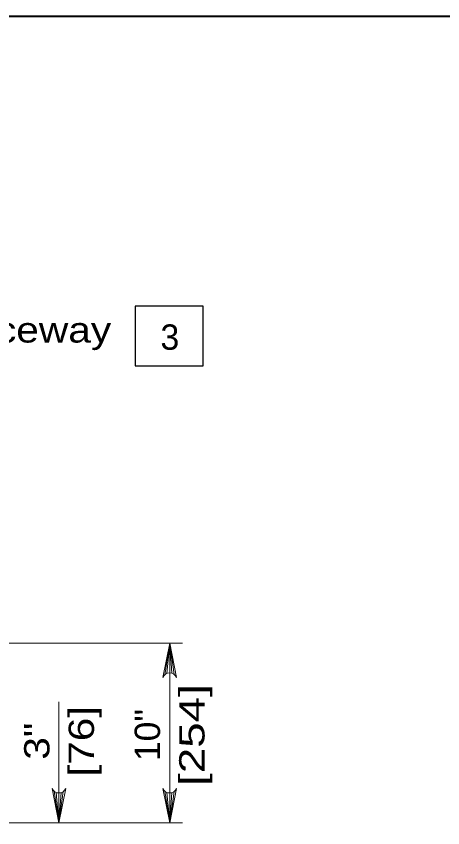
# Model space of a CAD drawing. Extents: x 1083.1 to 1123, y 697.4 to 741.4.
# Drawn here: x 1092.929 to 1095.554, y 713.855 to 718.854 of the extents above; entities that cross this region are included whole.
import ezdxf
from ezdxf.enums import TextEntityAlignment as Align

# ---------------------------------------------------------------- set-up
doc = ezdxf.new("R2010")
doc.units = 0
doc.header["$LTSCALE"] = 0.062
doc.layers.add('1', color=7, linetype='Continuous', lineweight=13)

msp = doc.modelspace()

# ---------------------------------------------------------------- linework, layer by layer
at = {"layer": '1', "lineweight": 25}
msp.add_line((1085.12642, 718.85408), (1116.62642, 718.85408), dxfattribs=at)
at = {"layer": '1'}
for p, q in [((1091.74475, 714.99225), (1093.95242, 714.99225)), ((1093.84408, 714.79808), (1093.87375, 714.99225)), ((1093.8565, 714.80542), (1093.87375, 714.99225)), ((1093.87375, 713.88608), (1093.87375, 714.99225)), ((1093.87375, 714.80883), (1093.87375, 714.99225)), ((1093.88733, 714.80683), (1093.87375, 714.99225)), ((1093.90058, 714.80033), (1093.87375, 714.99225)), ((1093.1915, 713.88608), (1093.1915, 714.63117)), ((1093.16175, 714.08033), (1093.1915, 713.88608)), ((1093.17425, 714.073), (1093.1915, 713.88608)), ((1093.21833, 714.07808), (1093.1915, 713.88608)), ((1093.205, 714.07158), (1093.1915, 713.88608)), ((1093.84408, 714.08033), (1093.87375, 713.88608)), ((1093.8565, 714.073), (1093.87375, 713.88608)), ((1093.90058, 714.07808), (1093.87375, 713.88608)), ((1093.88733, 714.07158), (1093.87375, 713.88608)), ((1093.1915, 714.06958), (1093.1915, 713.88608)), ((1093.87375, 714.06958), (1093.87375, 713.88608)), ((1092.35375, 713.88608), (1093.95242, 713.88608))]:
    msp.add_line(p, q, dxfattribs=at)
at = {"layer": '1', "lineweight": 40}
msp.add_lwpolyline([(1085.12642, 718.85408), (1116.62642, 718.85408), (1116.62642, 697.85408), (1085.12642, 697.85408)], close=True, dxfattribs=at)
at = {"layer": '1', "lineweight": 25}
msp.add_lwpolyline([(1093.66033, 717.06733), (1093.66033, 716.70058), (1094.07875, 716.70058), (1094.07875, 717.06733)], close=True, dxfattribs=at)
at = {"layer": '1'}
for points in [[(1093.83133, 714.78025), (1093.87375, 714.99225), (1093.91617, 714.78025)], [(1093.14908, 714.09817), (1093.1915, 713.88608), (1093.23383, 714.09817)], [(1093.83133, 714.09817), (1093.87375, 713.88608), (1093.91617, 714.09817)]]:
    msp.add_lwpolyline(points, dxfattribs=at)
for centre, start, end in [((1093.87378, 714.76313), 22.08782, 157.91395), ((1093.19151, 714.11527), 202.08605, 337.91218), ((1093.87378, 714.11527), 202.08605, 337.91218)]:
    msp.add_arc(centre, 0.04576, start, end, dxfattribs=at)

# ---------------------------------------------------------------- texts
at = {"layer": '1', "width": 1.2}
msp.add_text('Raceway', height=0.156, dxfattribs=at).set_placement((1092.48392, 716.84408))
at = {"layer": '1'}
msp.add_text('3', height=0.156, dxfattribs=at).set_placement((1093.81658, 716.79967))
for s, width, p in [('[254]', 1.35, (1094.08792, 714.42625)), ('[76]', 1.25, (1093.4075, 714.38842)), ('10"', 1.05, (1093.81392, 714.42625)), ('3"', 1.2, (1093.1335, 714.38846))]:
    msp.add_text(s, height=0.156, rotation=90, dxfattribs=dict(at, width=width)).set_placement(p, align=Align.CENTER)

doc.saveas('drawing.dxf')
